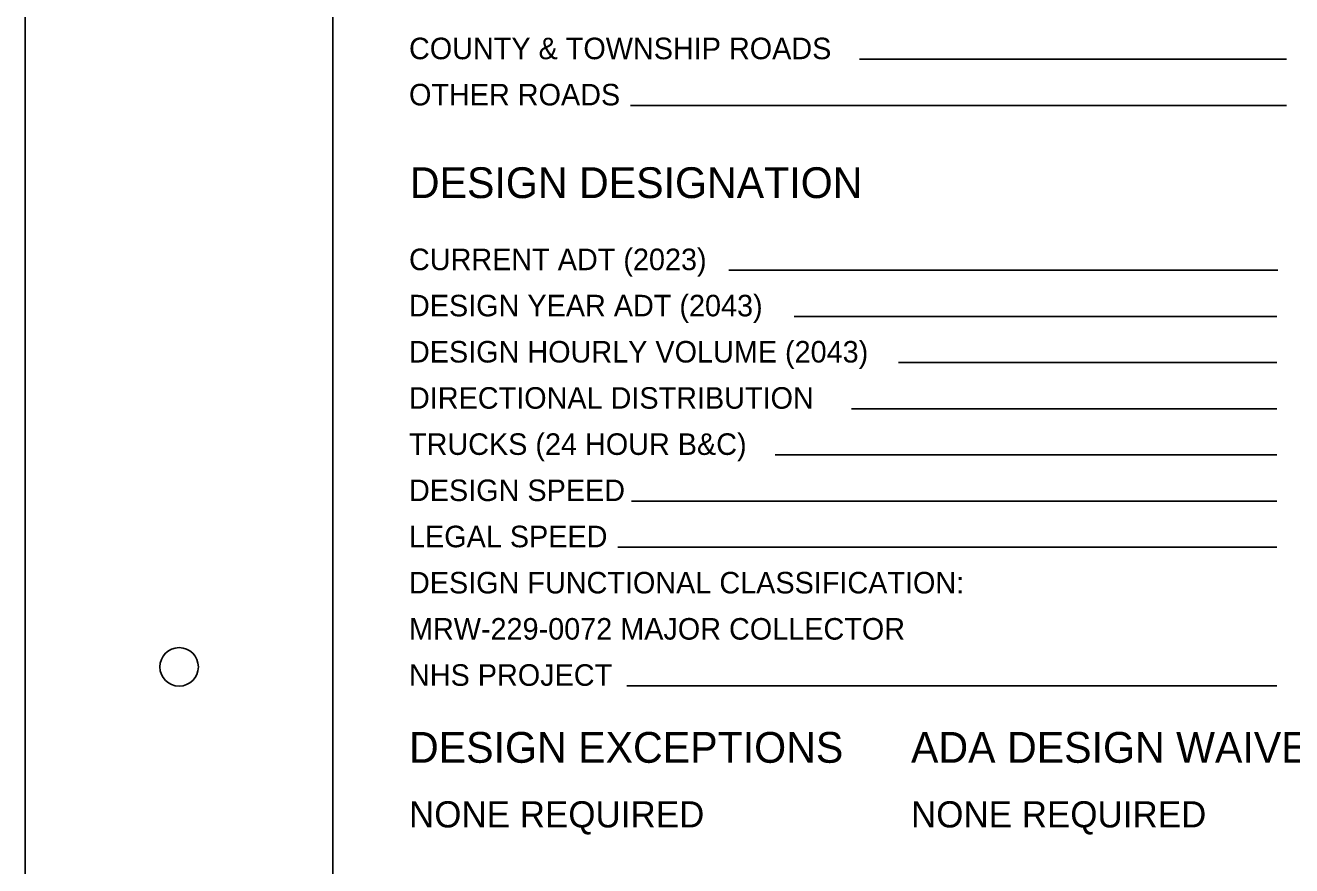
# Model space of a CAD drawing. Extents: x 0 to 34, y 0 to 22.
# Drawn here: x 0 to 8.23, y 5.46 to 10.92 of the extents above; entities that cross this region are included whole.
import ezdxf

# ---------------------------------------------------------------- set-up
doc = ezdxf.new("R2010")
doc.units = 0
for name, color, linetype in [('SH_Border', 7, 'Continuous'), ('SH_Cut_Line', 7, 'Continuous'), ('SH_Data', 7, 'Continuous')]:
    doc.layers.add(name, color=color, linetype=linetype)

msp = doc.modelspace()

# ---------------------------------------------------------------- linework, layer by layer
at = {"layer": 'SH_Border'}
msp.add_lwpolyline([(2, 21.5), (33.5, 21.5), (33.5, 0.5), (2, 0.5)], close=True, dxfattribs=at)
msp.add_circle((1, 6.75), 0.125, dxfattribs=at)
at = {"layer": 'SH_Cut_Line'}
msp.add_lwpolyline([(0, 0), (34, 0), (34, 22), (0, 22)], close=True, dxfattribs=at)
at = {"layer": 'SH_Data'}
for p, q in [((8.2, 10.6975), (5.424, 10.6975)), ((8.2, 10.3975), (3.9348, 10.3975)), ((8.1424, 9.3271), (4.5737, 9.3271)), ((8.1424, 9.3271), (4.5737, 9.3271)), ((8.1368, 9.0271), (4.9987, 9.0271)), ((8.1368, 9.0271), (4.9987, 9.0271)), ((8.1368, 8.7271), (5.6758, 8.7271)), ((8.1368, 8.7271), (5.6758, 8.7271)), ((8.1368, 8.4271), (5.3711, 8.4271)), ((8.1368, 8.4271), (5.3711, 8.4271)), ((8.1368, 8.1271), (4.8746, 8.1271)), ((8.1368, 8.1271), (4.8746, 8.1271)), ((8.1368, 7.8271), (3.9417, 7.8271)), ((8.1368, 7.8271), (3.9417, 7.8271)), ((8.1368, 7.5271), (3.8514, 7.5271)), ((8.1368, 7.5271), (3.8514, 7.5271)), ((8.1368, 6.6271), (3.9116, 6.6271)), ((8.1368, 6.6271), (3.9116, 6.6271))]:
    msp.add_line(p, q, dxfattribs=at)

# ---------------------------------------------------------------- texts
for s, height, p in [('COUNTY & TOWNSHIP ROADS', 0.14, (2.4944, 10.6975)), ('OTHER ROADS', 0.14, (2.4944, 10.3975)), ('DESIGN DESIGNATION', 0.2, (2.5, 9.7955)), ('DESIGN DESIGNATION', 0.2, (2.5, 9.7955)), ('CURRENT ADT (2023)', 0.14, (2.4944, 9.3271)), ('DESIGN YEAR ADT (2043)', 0.14, (2.4944, 9.0271)), ('DESIGN HOURLY VOLUME (2043)', 0.14, (2.4944, 8.7271)), ('DIRECTIONAL DISTRIBUTION', 0.14, (2.4944, 8.4271)), ('DIRECTIONAL DISTRIBUTION', 0.14, (2.4944, 8.4271)), ('TRUCKS (24 HOUR B&C)', 0.14, (2.4944, 8.1271)), ('TRUCKS (24 HOUR B&C)', 0.14, (2.4944, 8.1271)), ('DESIGN SPEED', 0.14, (2.4944, 7.8271)), ('DESIGN SPEED', 0.14, (2.4944, 7.8271)), ('LEGAL SPEED', 0.14, (2.4944, 7.5271)), ('LEGAL SPEED', 0.14, (2.4944, 7.5271)), ('DESIGN FUNCTIONAL CLASSIFICATION:', 0.14, (2.4944, 7.2271)), ('DESIGN FUNCTIONAL CLASSIFICATION:', 0.14, (2.4944, 7.2271)), ('MRW-229-0072 MAJOR COLLECTOR ', 0.14, (2.4944, 6.9271)), ('NHS PROJECT', 0.14, (2.4944, 6.6271)), ('NHS PROJECT', 0.14, (2.4944, 6.6271)), ('DESIGN EXCEPTIONS', 0.2, (2.4944, 6.1271)), ('DESIGN EXCEPTIONS', 0.2, (2.4944, 6.1271)), ('ADA DESIGN WAIVERS', 0.2, (5.7581, 6.1271)), ('NONE REQUIRED', 0.17, (2.4944, 5.7071)), ('NONE REQUIRED', 0.17, (5.7581, 5.7071))]:
    msp.add_text(s, height=height, dxfattribs=at).set_placement(p)

doc.saveas('drawing.dxf')
